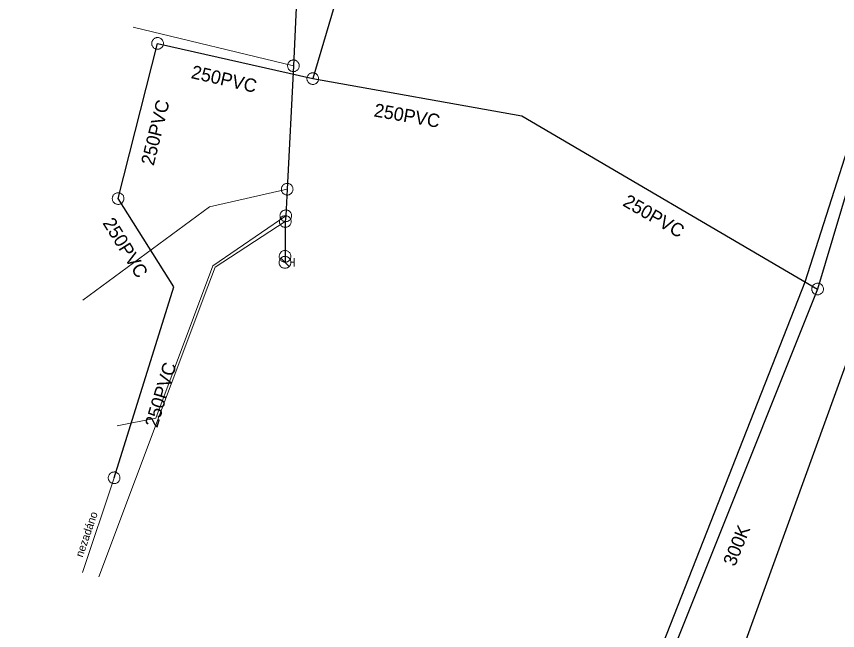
# Model space of a CAD drawing. Extents: x -741806 to -738704, y -1059275 to -1055387.
# Drawn here: x -740595 to -740533.4, y -1057880.2 to -1057834.2 of the extents above; entities that cross this region are included whole.
import ezdxf

# ---------------------------------------------------------------- set-up
doc = ezdxf.new("R2010")
doc.units = 0
doc.header["$LTSCALE"] = 0.4
for name, color, linetype, lineweight in [('2', 7, 'Continuous', 25), ('21', 7, 'Continuous', 13), ('3', 7, 'Continuous', 13), ('50', 7, 'Continuous', 13), ('51', 7, 'Continuous', 13), ('52', 7, 'Continuous', 25), ('56', 7, 'Continuous', 13)]:
    doc.layers.add(name, color=color, linetype=linetype, lineweight=lineweight)
doc.layers.add('5', color=7, linetype='Continuous')
doc.layers.add('55', color=7, linetype='Continuous')

msp = doc.modelspace()

# ---------------------------------------------------------------- linework, layer by layer
at = {"layer": '2'}
for p, q in [((-740566.01, -1057816.08), (-740572.78, -1057838.879)), ((-740584.42, -1057836.24), (-740572.78, -1057838.879)), ((-740529.84, -1057837.59), (-740534.91, -1057854.649)), ((-740572.78, -1057838.879), (-740557.1, -1057841.679)), ((-740557.1, -1057841.679), (-740534.91, -1057854.649)), ((-740587.68, -1057868.8), (-740583.21, -1057854.49))]:
    msp.add_line(p, q, dxfattribs=at)
for points in [[(-740609.006, -1057979.487), (-740608.671, -1057978.605), (-740585.671, -1057978.608), (-740567.046, -1057933.639), (-740552.184, -1057895.72), (-740535.835, -1057854.115), (-740530.462, -1057837.318), (-740525.059, -1057820.845), (-740524.232, -1057813.604), (-740512.355, -1057767.872), (-740507.212, -1057752.35), (-740500.784, -1057723.652), (-740491.688, -1057677.854), (-740489.039, -1057665.21)], [(-740583.21, -1057854.49), (-740587.379, -1057847.87), (-740584.42, -1057836.24)], [(-740534.91, -1057854.649), (-740551.41, -1057895.909), (-740566.21, -1057933.99)]]:
    msp.add_lwpolyline(points, dxfattribs=at)
at = {"layer": '21'}
msp.add_line((-740574.23, -1057837.919), (-740586.26, -1057835.02), dxfattribs=at)
for points in [[(-740574.699, -1057847.169), (-740580.53, -1057848.49), (-740590.02, -1057855.48)], [(-740574.8, -1057849.159), (-740580.28, -1057852.919), (-740584.539, -1057864.33), (-740587.46, -1057864.899)], [(-740574.84, -1057849.59), (-740580.1, -1057853.02), (-740580.66, -1057854.47), (-740588.829, -1057876.21)]]:
    msp.add_lwpolyline(points, dxfattribs=at)
at = {"layer": '3'}
for points in [[(-740584.311, -1057835.815), (-740584.355, -1057835.807), (-740584.401, -1057835.803), (-740584.447, -1057835.803), (-740584.492, -1057835.808), (-740584.537, -1057835.819), (-740584.581, -1057835.833), (-740584.622, -1057835.853), (-740584.662, -1057835.876), (-740584.698, -1057835.903), (-740584.731, -1057835.934), (-740584.762, -1057835.969), (-740584.789, -1057836.006), (-740584.81, -1057836.046), (-740584.829, -1057836.088), (-740584.843, -1057836.132), (-740584.852, -1057836.177), (-740584.855, -1057836.222), (-740584.855, -1057836.268), (-740584.85, -1057836.314), (-740584.839, -1057836.359), (-740584.824, -1057836.402), (-740584.806, -1057836.442), (-740584.782, -1057836.483), (-740584.755, -1057836.519), (-740584.724, -1057836.553), (-740584.689, -1057836.583), (-740584.652, -1057836.609), (-740584.612, -1057836.632), (-740584.57, -1057836.65), (-740584.526, -1057836.663), (-740584.482, -1057836.673), (-740584.436, -1057836.677), (-740584.39, -1057836.676), (-740584.344, -1057836.67), (-740584.3, -1057836.661), (-740584.256, -1057836.646), (-740584.215, -1057836.627), (-740584.175, -1057836.603), (-740584.139, -1057836.576), (-740584.106, -1057836.545), (-740584.075, -1057836.511), (-740584.048, -1057836.473), (-740584.026, -1057836.434), (-740584.008, -1057836.392), (-740583.995, -1057836.348), (-740583.985, -1057836.303), (-740583.981, -1057836.257), (-740583.982, -1057836.212), (-740583.987, -1057836.166), (-740583.998, -1057836.121), (-740584.013, -1057836.078), (-740584.031, -1057836.036), (-740584.055, -1057835.997), (-740584.082, -1057835.96), (-740584.113, -1057835.926), (-740584.148, -1057835.896), (-740584.185, -1057835.87), (-740584.225, -1057835.847), (-740584.267, -1057835.829), (-740584.31, -1057835.815)], [(-740572.352, -1057838.976), (-740572.345, -1057838.931), (-740572.342, -1057838.886), (-740572.344, -1057838.839), (-740572.35, -1057838.795), (-740572.362, -1057838.75), (-740572.378, -1057838.707), (-740572.398, -1057838.666), (-740572.422, -1057838.627), (-740572.451, -1057838.592), (-740572.482, -1057838.559), (-740572.518, -1057838.529), (-740572.556, -1057838.503), (-740572.596, -1057838.483), (-740572.639, -1057838.465), (-740572.683, -1057838.453), (-740572.728, -1057838.445), (-740572.774, -1057838.442), (-740572.819, -1057838.443), (-740572.865, -1057838.45), (-740572.91, -1057838.462), (-740572.952, -1057838.478), (-740572.992, -1057838.497), (-740573.032, -1057838.522), (-740573.068, -1057838.55), (-740573.101, -1057838.583), (-740573.13, -1057838.618), (-740573.155, -1057838.655), (-740573.177, -1057838.697), (-740573.194, -1057838.739), (-740573.206, -1057838.783), (-740573.214, -1057838.828), (-740573.217, -1057838.873), (-740573.215, -1057838.92), (-740573.208, -1057838.965), (-740573.198, -1057839.009), (-740573.182, -1057839.052), (-740573.161, -1057839.093), (-740573.136, -1057839.132), (-740573.109, -1057839.167), (-740573.077, -1057839.2), (-740573.042, -1057839.23), (-740573.004, -1057839.256), (-740572.963, -1057839.277), (-740572.921, -1057839.294), (-740572.876, -1057839.306), (-740572.831, -1057839.314), (-740572.786, -1057839.317), (-740572.74, -1057839.316), (-740572.694, -1057839.308), (-740572.65, -1057839.297), (-740572.607, -1057839.281), (-740572.566, -1057839.262), (-740572.527, -1057839.237), (-740572.491, -1057839.209), (-740572.458, -1057839.176), (-740572.429, -1057839.141), (-740572.404, -1057839.104), (-740572.382, -1057839.062), (-740572.366, -1057839.02), (-740572.353, -1057838.977)], [(-740587.612, -1057847.499), (-740587.648, -1057847.525), (-740587.682, -1057847.555), (-740587.714, -1057847.589), (-740587.741, -1057847.625), (-740587.765, -1057847.665), (-740587.784, -1057847.707), (-740587.798, -1057847.75), (-740587.809, -1057847.795), (-740587.814, -1057847.84), (-740587.815, -1057847.885), (-740587.811, -1057847.931), (-740587.802, -1057847.977), (-740587.788, -1057848.02), (-740587.771, -1057848.062), (-740587.748, -1057848.102), (-740587.722, -1057848.14), (-740587.691, -1057848.174), (-740587.658, -1057848.205), (-740587.621, -1057848.233), (-740587.581, -1057848.256), (-740587.54, -1057848.275), (-740587.497, -1057848.29), (-740587.452, -1057848.3), (-740587.407, -1057848.306), (-740587.361, -1057848.306), (-740587.315, -1057848.301), (-740587.271, -1057848.293), (-740587.226, -1057848.279), (-740587.184, -1057848.261), (-740587.144, -1057848.238), (-740587.107, -1057848.213), (-740587.073, -1057848.183), (-740587.041, -1057848.149), (-740587.014, -1057848.111), (-740586.991, -1057848.073), (-740586.971, -1057848.031), (-740586.957, -1057847.988), (-740586.947, -1057847.943), (-740586.942, -1057847.898), (-740586.941, -1057847.853), (-740586.945, -1057847.807), (-740586.953, -1057847.761), (-740586.967, -1057847.718), (-740586.985, -1057847.676), (-740587.007, -1057847.636), (-740587.034, -1057847.598), (-740587.064, -1057847.564), (-740587.097, -1057847.533), (-740587.134, -1057847.505), (-740587.174, -1057847.482), (-740587.216, -1057847.463), (-740587.258, -1057847.448), (-740587.303, -1057847.438), (-740587.348, -1057847.432), (-740587.395, -1057847.432), (-740587.441, -1057847.436), (-740587.485, -1057847.445), (-740587.529, -1057847.459), (-740587.571, -1057847.477), (-740587.611, -1057847.498)], [(-740535.035, -1057855.068), (-740534.991, -1057855.078), (-740534.946, -1057855.084), (-740534.899, -1057855.086), (-740534.854, -1057855.082), (-740534.809, -1057855.074), (-740534.764, -1057855.061), (-740534.723, -1057855.043), (-740534.682, -1057855.022), (-740534.645, -1057854.995), (-740534.61, -1057854.966), (-740534.578, -1057854.933), (-740534.55, -1057854.896), (-740534.527, -1057854.857), (-740534.506, -1057854.816), (-740534.491, -1057854.773), (-740534.48, -1057854.728), (-740534.475, -1057854.683), (-740534.473, -1057854.637), (-740534.477, -1057854.591), (-740534.485, -1057854.546), (-740534.498, -1057854.503), (-740534.515, -1057854.461), (-740534.537, -1057854.42), (-740534.563, -1057854.382), (-740534.593, -1057854.347), (-740534.627, -1057854.316), (-740534.662, -1057854.288), (-740534.702, -1057854.264), (-740534.743, -1057854.244), (-740534.786, -1057854.229), (-740534.83, -1057854.218), (-740534.875, -1057854.212), (-740534.922, -1057854.211), (-740534.968, -1057854.215), (-740535.012, -1057854.223), (-740535.056, -1057854.236), (-740535.098, -1057854.253), (-740535.139, -1057854.276), (-740535.176, -1057854.301), (-740535.211, -1057854.33), (-740535.243, -1057854.364), (-740535.271, -1057854.4), (-740535.295, -1057854.439), (-740535.315, -1057854.48), (-740535.33, -1057854.524), (-740535.341, -1057854.568), (-740535.347, -1057854.613), (-740535.348, -1057854.659), (-740535.344, -1057854.705), (-740535.336, -1057854.75), (-740535.323, -1057854.794), (-740535.306, -1057854.836), (-740535.283, -1057854.876), (-740535.258, -1057854.914), (-740535.228, -1057854.949), (-740535.195, -1057854.981), (-740535.159, -1057855.008), (-740535.119, -1057855.033), (-740535.078, -1057855.052), (-740535.036, -1057855.068)], [(-740587.548, -1057868.382), (-740587.592, -1057868.371), (-740587.637, -1057868.364), (-740587.684, -1057868.362), (-740587.729, -1057868.365), (-740587.774, -1057868.373), (-740587.819, -1057868.385), (-740587.861, -1057868.402), (-740587.902, -1057868.423), (-740587.939, -1057868.449), (-740587.975, -1057868.478), (-740588.007, -1057868.511), (-740588.036, -1057868.547), (-740588.059, -1057868.585), (-740588.081, -1057868.626), (-740588.096, -1057868.669), (-740588.108, -1057868.714), (-740588.114, -1057868.759), (-740588.116, -1057868.804), (-740588.113, -1057868.851), (-740588.105, -1057868.896), (-740588.093, -1057868.94), (-740588.076, -1057868.981), (-740588.055, -1057869.023), (-740588.03, -1057869.061), (-740588, -1057869.096), (-740587.967, -1057869.128), (-740587.932, -1057869.156), (-740587.893, -1057869.181), (-740587.852, -1057869.201), (-740587.808, -1057869.217), (-740587.765, -1057869.229), (-740587.72, -1057869.235), (-740587.673, -1057869.237), (-740587.627, -1057869.234), (-740587.583, -1057869.227), (-740587.538, -1057869.214), (-740587.496, -1057869.197), (-740587.455, -1057869.176), (-740587.418, -1057869.151), (-740587.383, -1057869.122), (-740587.35, -1057869.089), (-740587.321, -1057869.053), (-740587.297, -1057869.014), (-740587.277, -1057868.974), (-740587.261, -1057868.93), (-740587.249, -1057868.886), (-740587.242, -1057868.841), (-740587.241, -1057868.795), (-740587.244, -1057868.749), (-740587.252, -1057868.704), (-740587.264, -1057868.66), (-740587.28, -1057868.617), (-740587.302, -1057868.577), (-740587.327, -1057868.539), (-740587.357, -1057868.503), (-740587.39, -1057868.471), (-740587.425, -1057868.443), (-740587.465, -1057868.418), (-740587.505, -1057868.398), (-740587.547, -1057868.382)]]:
    msp.add_lwpolyline(points, dxfattribs=at)
at = {"layer": '50'}
for p, q in [((-740574.863, -1057852.648), (-740575.18, -1057852.331)), ((-740574.863, -1057852.648), (-740574.551, -1057852.964)), ((-740574.416, -1057852.648), (-740574.165, -1057852.648)), ((-740574.165, -1057852.34), (-740574.165, -1057852.648)), ((-740574.165, -1057852.955), (-740574.165, -1057852.648))]:
    msp.add_line(p, q, dxfattribs=at)
msp.add_lwpolyline([(-740574.867, -1057853.092), (-740574.818, -1057853.09), (-740574.772, -1057853.085), (-740574.726, -1057853.072), (-740574.683, -1057853.055), (-740574.643, -1057853.036), (-740574.602, -1057853.009), (-740574.567, -1057852.98), (-740574.532, -1057852.947), (-740574.502, -1057852.912), (-740574.478, -1057852.872), (-740574.456, -1057852.831), (-740574.437, -1057852.788), (-740574.427, -1057852.742), (-740574.419, -1057852.696), (-740574.416, -1057852.65), (-740574.419, -1057852.604), (-740574.424, -1057852.559), (-740574.437, -1057852.513), (-740574.454, -1057852.469), (-740574.475, -1057852.426), (-740574.5, -1057852.388), (-740574.529, -1057852.351), (-740574.562, -1057852.318), (-740574.597, -1057852.289), (-740574.637, -1057852.262), (-740574.678, -1057852.24), (-740574.721, -1057852.224), (-740574.767, -1057852.21), (-740574.813, -1057852.205), (-740574.859, -1057852.198), (-740574.907, -1057852.201), (-740574.953, -1057852.209), (-740574.996, -1057852.22), (-740575.042, -1057852.236), (-740575.083, -1057852.258), (-740575.123, -1057852.282), (-740575.158, -1057852.312), (-740575.193, -1057852.344), (-740575.223, -1057852.382), (-740575.247, -1057852.42), (-740575.269, -1057852.463), (-740575.285, -1057852.506), (-740575.299, -1057852.549), (-740575.307, -1057852.598), (-740575.31, -1057852.644), (-740575.307, -1057852.69), (-740575.299, -1057852.736), (-740575.288, -1057852.782), (-740575.272, -1057852.825), (-740575.25, -1057852.868), (-740575.226, -1057852.906), (-740575.196, -1057852.944), (-740575.164, -1057852.976), (-740575.129, -1057853.006), (-740575.088, -1057853.03), (-740575.048, -1057853.054), (-740575.004, -1057853.071), (-740574.959, -1057853.081), (-740574.913, -1057853.089)], close=True, dxfattribs=at)
at = {"layer": '51'}
for points in [[(-740574.654, -1057837.816), (-740574.663, -1057837.86), (-740574.667, -1057837.905), (-740574.665, -1057837.952), (-740574.66, -1057837.996), (-740574.649, -1057838.041), (-740574.634, -1057838.085), (-740574.614, -1057838.126), (-740574.59, -1057838.165), (-740574.562, -1057838.201), (-740574.531, -1057838.234), (-740574.496, -1057838.264), (-740574.458, -1057838.291), (-740574.418, -1057838.313), (-740574.376, -1057838.33), (-740574.332, -1057838.343), (-740574.287, -1057838.352), (-740574.241, -1057838.355), (-740574.196, -1057838.354), (-740574.15, -1057838.348), (-740574.105, -1057838.337), (-740574.062, -1057838.321), (-740574.021, -1057838.303), (-740573.982, -1057838.278), (-740573.945, -1057838.251), (-740573.912, -1057838.219), (-740573.882, -1057838.184), (-740573.857, -1057838.147), (-740573.834, -1057838.106), (-740573.817, -1057838.064), (-740573.803, -1057838.02), (-740573.796, -1057837.975), (-740573.792, -1057837.93), (-740573.793, -1057837.883), (-740573.799, -1057837.839), (-740573.81, -1057837.794), (-740573.825, -1057837.75), (-740573.845, -1057837.709), (-740573.868, -1057837.67), (-740573.897, -1057837.634), (-740573.928, -1057837.601), (-740573.963, -1057837.571), (-740574, -1057837.544), (-740574.041, -1057837.523), (-740574.082, -1057837.505), (-740574.127, -1057837.492), (-740574.172, -1057837.483), (-740574.218, -1057837.481), (-740574.263, -1057837.481), (-740574.309, -1057837.487), (-740574.353, -1057837.498), (-740574.396, -1057837.514), (-740574.438, -1057837.532), (-740574.477, -1057837.557), (-740574.513, -1057837.584), (-740574.547, -1057837.616), (-740574.577, -1057837.651), (-740574.602, -1057837.688), (-740574.624, -1057837.729), (-740574.641, -1057837.771), (-740574.654, -1057837.815)], [(-740575.125, -1057847.265), (-740575.113, -1057847.308), (-740575.096, -1057847.35), (-740575.075, -1057847.392), (-740575.05, -1057847.429), (-740575.02, -1057847.464), (-740574.987, -1057847.497), (-740574.951, -1057847.525), (-740574.913, -1057847.55), (-740574.871, -1057847.569), (-740574.829, -1057847.585), (-740574.784, -1057847.596), (-740574.738, -1057847.604), (-740574.693, -1057847.606), (-740574.647, -1057847.602), (-740574.602, -1057847.594), (-740574.558, -1057847.582), (-740574.515, -1057847.565), (-740574.475, -1057847.544), (-740574.437, -1057847.518), (-740574.402, -1057847.488), (-740574.37, -1057847.456), (-740574.341, -1057847.42), (-740574.317, -1057847.381), (-740574.297, -1057847.34), (-740574.281, -1057847.297), (-740574.269, -1057847.252), (-740574.263, -1057847.208), (-740574.261, -1057847.161), (-740574.264, -1057847.116), (-740574.272, -1057847.07), (-740574.285, -1057847.027), (-740574.301, -1057846.985), (-740574.323, -1057846.944), (-740574.348, -1057846.906), (-740574.377, -1057846.871), (-740574.41, -1057846.838), (-740574.446, -1057846.81), (-740574.485, -1057846.785), (-740574.526, -1057846.766), (-740574.569, -1057846.75), (-740574.613, -1057846.739), (-740574.659, -1057846.731), (-740574.704, -1057846.73), (-740574.75, -1057846.733), (-740574.795, -1057846.741), (-740574.84, -1057846.753), (-740574.882, -1057846.771), (-740574.922, -1057846.791), (-740574.961, -1057846.817), (-740574.996, -1057846.847), (-740575.027, -1057846.88), (-740575.056, -1057846.915), (-740575.08, -1057846.954), (-740575.101, -1057846.995), (-740575.117, -1057847.038), (-740575.128, -1057847.083), (-740575.134, -1057847.127), (-740575.136, -1057847.174), (-740575.133, -1057847.219), (-740575.125, -1057847.264)], [(-740575.206, -1057849.828), (-740575.18, -1057849.864), (-740575.149, -1057849.898), (-740575.114, -1057849.929), (-740575.078, -1057849.956), (-740575.038, -1057849.979), (-740574.996, -1057849.998), (-740574.953, -1057850.011), (-740574.908, -1057850.021), (-740574.862, -1057850.025), (-740574.817, -1057850.025), (-740574.771, -1057850.021), (-740574.726, -1057850.011), (-740574.682, -1057849.997), (-740574.641, -1057849.979), (-740574.601, -1057849.955), (-740574.564, -1057849.928), (-740574.53, -1057849.898), (-740574.499, -1057849.864), (-740574.473, -1057849.826), (-740574.45, -1057849.786), (-740574.432, -1057849.744), (-740574.417, -1057849.701), (-740574.408, -1057849.656), (-740574.403, -1057849.611), (-740574.403, -1057849.565), (-740574.408, -1057849.519), (-740574.418, -1057849.475), (-740574.432, -1057849.431), (-740574.451, -1057849.389), (-740574.473, -1057849.349), (-740574.501, -1057849.313), (-740574.531, -1057849.279), (-740574.566, -1057849.248), (-740574.602, -1057849.221), (-740574.642, -1057849.199), (-740574.684, -1057849.18), (-740574.728, -1057849.166), (-740574.772, -1057849.156), (-740574.818, -1057849.152), (-740574.863, -1057849.152), (-740574.909, -1057849.157), (-740574.954, -1057849.166), (-740574.997, -1057849.181), (-740575.039, -1057849.199), (-740575.079, -1057849.222), (-740575.116, -1057849.249), (-740575.15, -1057849.28), (-740575.181, -1057849.314), (-740575.207, -1057849.351), (-740575.23, -1057849.391), (-740575.248, -1057849.433), (-740575.263, -1057849.476), (-740575.272, -1057849.521), (-740575.277, -1057849.566), (-740575.277, -1057849.613), (-740575.272, -1057849.658), (-740575.263, -1057849.702), (-740575.248, -1057849.747), (-740575.229, -1057849.788), (-740575.206, -1057849.827)], [(-740575.16, -1057849.405), (-740575.133, -1057849.441), (-740575.102, -1057849.474), (-740575.066, -1057849.505), (-740575.029, -1057849.53), (-740574.989, -1057849.552), (-740574.946, -1057849.57), (-740574.903, -1057849.583), (-740574.858, -1057849.592), (-740574.812, -1057849.595), (-740574.767, -1057849.594), (-740574.721, -1057849.588), (-740574.676, -1057849.577), (-740574.633, -1057849.562), (-740574.592, -1057849.543), (-740574.553, -1057849.518), (-740574.516, -1057849.491), (-740574.483, -1057849.46), (-740574.453, -1057849.425), (-740574.427, -1057849.386), (-740574.405, -1057849.346), (-740574.388, -1057849.304), (-740574.374, -1057849.26), (-740574.367, -1057849.215), (-740574.362, -1057849.17), (-740574.364, -1057849.123), (-740574.37, -1057849.078), (-740574.38, -1057849.034), (-740574.396, -1057848.99), (-740574.416, -1057848.949), (-740574.439, -1057848.909), (-740574.467, -1057848.874), (-740574.498, -1057848.841), (-740574.534, -1057848.811), (-740574.571, -1057848.785), (-740574.611, -1057848.763), (-740574.654, -1057848.745), (-740574.698, -1057848.733), (-740574.743, -1057848.724), (-740574.788, -1057848.721), (-740574.834, -1057848.722), (-740574.879, -1057848.728), (-740574.924, -1057848.738), (-740574.967, -1057848.754), (-740575.009, -1057848.773), (-740575.048, -1057848.797), (-740575.084, -1057848.825), (-740575.117, -1057848.857), (-740575.147, -1057848.891), (-740575.173, -1057848.929), (-740575.195, -1057848.969), (-740575.212, -1057849.012), (-740575.226, -1057849.055), (-740575.234, -1057849.1), (-740575.238, -1057849.146), (-740575.236, -1057849.192), (-740575.23, -1057849.238), (-740575.22, -1057849.281), (-740575.204, -1057849.325), (-740575.184, -1057849.366), (-740575.161, -1057849.405)], [(-740574.862, -1057852.636), (-740574.817, -1057852.635), (-740574.772, -1057852.628), (-740574.727, -1057852.617), (-740574.685, -1057852.601), (-740574.644, -1057852.58), (-740574.605, -1057852.555), (-740574.569, -1057852.527), (-740574.536, -1057852.495), (-740574.508, -1057852.459), (-740574.483, -1057852.421), (-740574.461, -1057852.381), (-740574.444, -1057852.338), (-740574.432, -1057852.294), (-740574.424, -1057852.249), (-740574.422, -1057852.203), (-740574.424, -1057852.157), (-740574.43, -1057852.112), (-740574.442, -1057852.068), (-740574.459, -1057852.025), (-740574.479, -1057851.983), (-740574.504, -1057851.945), (-740574.532, -1057851.909), (-740574.565, -1057851.877), (-740574.599, -1057851.847), (-740574.638, -1057851.822), (-740574.679, -1057851.801), (-740574.721, -1057851.785), (-740574.766, -1057851.772), (-740574.811, -1057851.765), (-740574.857, -1057851.762), (-740574.902, -1057851.764), (-740574.947, -1057851.771), (-740574.992, -1057851.782), (-740575.034, -1057851.798), (-740575.075, -1057851.819), (-740575.114, -1057851.844), (-740575.15, -1057851.872), (-740575.183, -1057851.904), (-740575.211, -1057851.94), (-740575.236, -1057851.978), (-740575.258, -1057852.018), (-740575.275, -1057852.061), (-740575.286, -1057852.105), (-740575.295, -1057852.15), (-740575.297, -1057852.196), (-740575.295, -1057852.242), (-740575.288, -1057852.287), (-740575.277, -1057852.331), (-740575.26, -1057852.374), (-740575.24, -1057852.416), (-740575.215, -1057852.454), (-740575.187, -1057852.49), (-740575.154, -1057852.522), (-740575.12, -1057852.552), (-740575.081, -1057852.577), (-740575.04, -1057852.598), (-740574.998, -1057852.614), (-740574.953, -1057852.627), (-740574.908, -1057852.634), (-740574.863, -1057852.636)]]:
    msp.add_lwpolyline(points, dxfattribs=at)
at = {"layer": '52'}
for points in [[(-740489.868, -1057679.99), (-740497.519, -1057704.287), (-740502.89, -1057727.946), (-740504.09, -1057731.52), (-740504.16, -1057731.78), (-740504.295, -1057732.394), (-740505.458, -1057737.884), (-740512.487, -1057766.415), (-740507.033, -1057770.061), (-740517.328, -1057816.22), (-740521.664, -1057829.6), (-740544.85, -1057893.509), (-740554.399, -1057919.446), (-740570.451, -1057950.712), (-740592.697, -1058007.398), (-740600.714, -1058010.487), (-740613.05, -1058039.97), (-740626.485, -1058069.3)], [(-740568.079, -1057794.71), (-740568.149, -1057794.929), (-740572.09, -1057813.29), (-740572.92, -1057818.389), (-740573.71, -1057826.429), (-740574.23, -1057837.919), (-740574.699, -1057847.169), (-740574.8, -1057849.159), (-740574.84, -1057849.59), (-740574.859, -1057852.2), (-740574.859, -1057852.649)]]:
    msp.add_lwpolyline(points, dxfattribs=at)
at = {"layer": '56'}
msp.add_line((-740590.059, -1057875.889), (-740587.68, -1057868.8), dxfattribs=at)

# ---------------------------------------------------------------- texts
at = {"layer": '5'}
for s, rotation, p in [('250PVC', 347, (-740581.964, -1057838.832)), ('250PVC', 76, (-740584.715, -1057845.451)), ('250PVC', 350, (-740568.242, -1057841.706)), ('250PVC', 330, (-740549.596, -1057848.364)), ('250PVC', 302, (-740588.573, -1057849.699)), ('250PVC', 73, (-740584.444, -1057865.099)), ('300K', 68, (-740541.109, -1057875.5))]:
    msp.add_text(s, height=1, rotation=rotation, dxfattribs=at).set_placement(p)
at = {"layer": '55'}
msp.add_text('nezadáno  ', height=0.6, rotation=71, dxfattribs=at).set_placement((-740590.041, -1057874.799))

doc.saveas('drawing.dxf')
